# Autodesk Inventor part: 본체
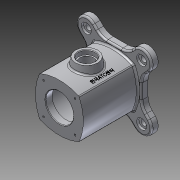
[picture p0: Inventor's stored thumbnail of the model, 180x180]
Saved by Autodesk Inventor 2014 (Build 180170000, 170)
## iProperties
Created: 2016-05
Part Number: 본체
Material: 알루미늄 6061
Document SubType Name: Modeling
Designer: J.H.CHAE
Density: 2.71 g/cm^3
Appearance: 알루미늄 - 평지
Mass: 1111.8 g
Surface Area: 864.181 cm^2
Volume: 410.257 cm^3
Author: J.H.CHAE
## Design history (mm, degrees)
sketch "스케치1"
  geometry: L1 (35.355, 35.355)-(-35.355, 35.355); L2 (-35.355, 35.355)-(-35.355, -35.355); L3 (-35.355, -35.355)-(35.355, -35.355); L4 (35.355, -35.355)-(35.355, 35.355); A1 r 85.579 centre (0, -42.579) between (35.355, 35.355) and (-35.355, 35.355); A2 r 85.579 centre (42.579, 0) between (-35.355, 35.355) and (-35.355, -35.355); A3 r 85.579 centre (0, 42.579) between (-35.355, -35.355) and (35.355, -35.355); A4 r 85.579 centre (-42.579, 0) between (35.355, -35.355) and (35.355, 35.355); 3 further points
  constraints: 9 end point, 8 point on circle, 4 centre point, 3 equal radius, 2 midpoint, 2 parallel, 2 perpendicular, 1 horizontal, 1 horizontal alignment, 1 vertical alignment
  dimensions: "d0" = 86 dimension on A2 A4; "d1" = 100 distance of L3.end L1.end
extrude "돌출1" new body sketch "스케치1" distance "d2" = 98; taper "d3" = 0 deg
sketch "스케치2"
  geometry: L1 (0, 0)-(-49.497, -49.497); L2 (0, 0)-(-70, 0); L3 (-49, -49)-(49, -49); L4 (49, -49)-(49, 49); L5 (49, 49)-(-49, 49); L6 (-49, 49)-(-49, -49); L7 (-49, -49)-(49, 49); L8 (49, -49)-(-49, 49); L9 (0, 98)-(0, -98) reference; L10 (62.225, -36.77)-(49, -23.544); L11 (36.77, -62.225)-(23.544, -49); L12 (62.225, 36.77)-(49, 23.544); L13 (36.77, 62.225)-(23.544, 49); L14 (-62.225, -36.77)-(-49, -23.544); L15 (-36.77, -62.225)-(-23.544, -49); L16 (-36.77, 62.225)-(-23.544, 49); L17 (-62.225, 36.77)-(-49, 23.544); A1 r 70 centre (0, 0) between (-49.497, -49.497) and (-70, 0); A2 r 18 centre (-49.497, -49.497) between (-36.77, -62.225) and (-62.225, -36.77); A3 r 18 centre (49.497, -49.497) between (62.225, -36.77) and (49, -31.504); A4 r 18 centre (49.497, 49.497) between (36.77, 62.225) and (62.225, 36.77); A5 r 18 centre (-49.497, 49.497) between (-62.225, 36.77) and (-36.77, 62.225); 9 further points
  constraints: 32 end point, 23 point on line, 17 symmetric about line, 11 point on circle, 5 centre point, 3 parallel, 2 coincident, 2 horizontal, 2 midpoint, 2 perpendicular, 1 tangent, 3 other
  dimensions: "d4" = 140 diameter of A1; "d5" = 45 deg angle of L1 L2; "d6" = 98 distance of L4.end L5.end; "d7" = 36 diameter of A2
extrude "돌출2" join sketch "스케치2" distance "d8" = 12; taper "d9" = 0 deg
sketch "스케치3"
  geometry: L1 (49, 55)-(69, 55); L2 (69, 55)-(69, 0); L3 (69, 0)-(49, 0); L4 (49, 0)-(49, 55); L5 (0, -35.355)-(0, 35.355) reference; L6 (-22, 0)-(132, 0) reference; 1 further point
  constraints: 8 end point, 2 parallel, 1 collinear, 1 horizontal, 1 perpendicular
  dimensions: "d12" = 55 distance from line of point (0, 0) L1; "d13" = 40 diameter of L2 L4; "d14" = 49 distance between parallel lines of L4 L5
revolve "회전1" sketch "스케치3" stored, may be unused: angle "d15" = 90 deg
sketch "스케치4"
  geometry: 1 further point
hole "구멍1" sketch "스케치4" at (0, 0) diameter "d16" = 50; stored, may be unused: countersink angle "d20" = 90 deg, drill point angle "d22" = 0 deg; dims "d17" = 6, "d18" = 4, "d19" = 2, "d21" = 12
hole "구멍2" diameter "d25" = 70; stored, may be unused: countersink angle "d29" = 90 deg, drill point angle "d31" = 0 deg; dims "d23" = 10, "d24" = 10, "d26" = 6, "d27" = 4, "d28" = 2, "d30" = 86
sketch "스케치5"
  geometry: 1 further point
hole "구멍3" sketch "스케치5" at (0, 0) diameter "d32" = 50; stored, may be unused: countersink angle "d36" = 90 deg, drill point angle "d38" = 0 deg; dims "d33" = 6, "d34" = 4, "d35" = 2, "d37" = 12
hole "구멍4" diameter "d41" = 10; stored, may be unused: countersink angle "d45" = 90 deg, drill point angle "d47" = 0 deg; dims "d39" = 10, "d40" = 10, "d42" = 6, "d43" = 18, "d44" = 4, "d46" = 12
sketch "스케치6" dims "d51" = 80
  geometry: L1 (0, 0)-(28.284, 28.284); L2 (-94.496, 0)-(94.496, 0) reference; 1 further point
  constraints: 2 end point, 1 coincident, 3 other
  dimensions: "d52" = 45 deg angle of L2 L1
hole "구멍5" sketch "스케치6" at (28.284, 28.284) diameter "d53" = 3.242; stored, may be unused: countersink angle "d57" = 90 deg, drill point angle "d59" = 118 deg; dims "d54" = 7, "d55" = 18, "d56" = 4, "d58" = 10
sketch "스케치7" dims "d63" = 80
  geometry: L1 (0, 0)-(-28.284, -28.284); L2 (-94.496, 0)-(94.496, 0) reference; 1 further point
  constraints: 2 end point, 1 coincident, 3 other
  dimensions: "d64" = 45 deg angle of L2 L1
hole "구멍6" sketch "스케치7" at (-28.284, -28.284) diameter "d65" = 3.242; stored, may be unused: countersink angle "d69" = 90 deg, drill point angle "d71" = 118 deg; dims "d66" = 7, "d67" = 18, "d68" = 4, "d70" = 10
hole "구멍7" diameter "d77" = 25; stored, may be unused: countersink angle "d81" = 90 deg, drill point angle "d83" = 0 deg; dims "d75" = 10, "d76" = 10, "d78" = 7, "d79" = 30, "d80" = 8, "d82" = 10
fillet "모깎기3" dims "d86" = 3
chamfer "모따기1" distance "d88" = 1; stored, may be unused: second distance "d89" = 2, angle "d90" = 45 deg
chamfer "모따기2" distance "d91" = 1; stored, may be unused: second distance "d92" = 2, angle "d93" = 45 deg
fillet "모깎기5" dims "d94" = 3
feature "면 기울기2" dims angle "d95" = 10 deg
fillet "모깎기6" dims "d96" = 3
fillet "모깎기7" dims "d97" = 3
sketch "스케치8"
  geometry: L1 (0, 0)-(29, 37.937); A1 r 85.579 centre (0, -42.579) between (34.285, 35.832) and (-34.285, 35.832) reference; A2 r 85.579 centre (-42.579, 0) between (35.832, -34.285) and (35.832, 34.285) reference
  constraints: 2 end point, 1 point on circle
  dimensions: "d98" = 29 horizontal distance of L1.start L1.end
fillet "모깎기8" dims "d104" = 25
fillet "모깎기9" dims "d105" = 3
node "작업 평면5"
feature "엠보싱2" dims "d0" = 86, "d1" = 100, "d7" = 36, "d108" = 0.5, "d109" = 0
node "솔리드1"
pattern_circular "원형 패턴1" dims angle "d49" = 360 deg
pattern_circular "원형 패턴2" dims angle "d61" = 360 deg
pattern_circular "원형 패턴3" dims angle "d73" = 360 deg
sketch "스케치10"
  geometry: L1 (0, -5.686)-(0, 58.828) reference; L2 (49, 30.355)-(125.093, 30.355); 2 further points; 1 other entity
  constraints: 2 end point, 1 perpendicular, 2 other
  dimensions: "d107" = 49 distance from line of L1 point (49, 1.355); "d110" = 29 distance from line of point (49, 1.355) L2
